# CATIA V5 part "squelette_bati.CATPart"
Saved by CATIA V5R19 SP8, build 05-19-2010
Part number: squelette_bati
Publications: "Point.6", "Point.5", "Point.4", "Point.3", "Droite.3", "Point.2", "Point.1", "Droite.2", "Droite.6", "Droite.7", "Plan.1"
Bounding box of the stored display mesh (mm): x -49.964 to 45, y 0 to 66.858, z -500 to 345.816
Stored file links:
  G:\EU_thinkMotion\CFAO_2010\SIL_groupe1\SIL_groupe1\A reprendre\lalpha\lalpha\Alpha.mécanisme\squelette_bati.CATPart
  D:\Documents\IFMA\S3\CFAO\projet_CFAO\squelette_mecanisme.CATPart
  Produit2.CATProduct
  G:\EU_thinkMotion\CFAO_2010\SIL_groupe1\SIL_groupe1\A reprendre\lalpha\lalpha\Alpha.mécanisme\squelette_piece_7.CATPart
  G:\EU_thinkMotion\CFAO_2010\SIL_groupe1\SIL_groupe1\A reprendre\lalpha\lalpha\Alpha.mécanisme\bielle7.CATPart
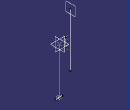
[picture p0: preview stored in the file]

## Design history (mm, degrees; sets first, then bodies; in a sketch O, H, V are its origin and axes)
Set1
  Line1: type PtPt, FirstPoint Point1, SecondPoint Point2
  Point1: stored without definition
  Point2: stored without definition
  Line2: type PtPt, FirstPoint Point3, SecondPoint Point4, Start 25, End 25
  Point3: stored without definition
  Point4: stored without definition
  Point5: (0, 0, 0), relative to Point6
  Point6 to Point8: stored without definition
  Line3: type PtPt, FirstPoint Point7, SecondPoint Point8
  Line4: stored without definition
  Plane1: type OffsetPt, RefPlane yz-plane, RefPoint vertex of Line4
Body1 (main body)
